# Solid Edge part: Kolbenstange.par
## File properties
Username: ahadarics
Dokumentum tartalom típus: 0
Author: ahadarics
Last saved by: ahadarics
Revision: 79
Sűrűség: 0,000 kg/m^3
Pontosság: 0,990
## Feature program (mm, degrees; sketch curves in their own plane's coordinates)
base feature "unnamed BaseFeature 1"
thread "unnamed Thread 1"
sketch for "Kihúzás_1" plane through (59.75, 0, 0) normal (1, 0, 0) x-axis (0, -1, 0)
  circle centre (0, 0) radius 10
extrude "Kihúzás_1" add finite 32 along -normal
chamfer "Letörés_1" setback 0.4
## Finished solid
Body 1: solid body, 13 faces, 23 edges, 12 vertices.
  Faces by surface: plane 9, cylinder 3, cone 1
  Edges by curve: line 12, circle 11
Bounding box of the edges (mm): 173.500 x 20.000 x 20.000, from (-113.75, -10, -10) to (59.75, 10, 10).
Cylindrical faces by radius (mm): R4 x2, R10 x1
Conical faces (half-angle, radius in mm at the cone's reference point): 45 deg R3.6 x1
Planar faces by outward normal: +x 3, +z 1, -x 4, -z 1
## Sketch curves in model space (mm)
circle centre (59.75, 0, 0) radius 10
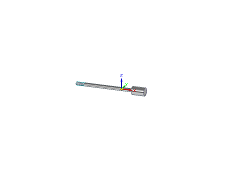
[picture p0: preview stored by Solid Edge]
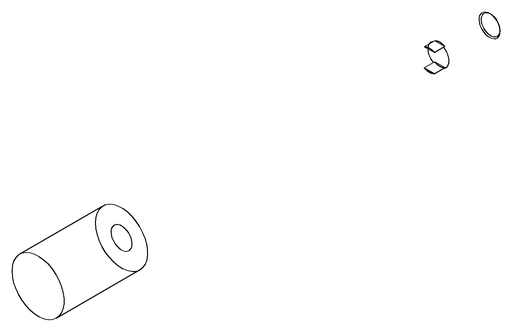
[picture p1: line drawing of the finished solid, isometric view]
